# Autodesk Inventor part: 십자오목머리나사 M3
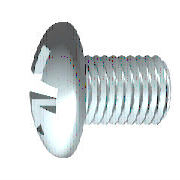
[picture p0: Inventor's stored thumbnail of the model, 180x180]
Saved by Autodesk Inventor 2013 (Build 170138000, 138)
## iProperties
Created: 2012-02
Part Number: 십자오목머리나사 M3
Material: 강철, 연강
Description: 십자 오목 머리 나사
Document SubType Name: Modeling
Standard: KS B 1023
Designer: mduedu
Standards Organization: KS
Language: ko-KR
Size Designation: A  M 3 x 6 - H
Categories: <MemberInstance><Categories><Category DisplayName="조임쇠" InternalName="e4da775c-781d-43d5-af7c-5136215cf5a6" Mnemonic="FSTN"><Category DisplayName="볼트" InternalN
Density: 7.86 g/cm^3
Mass: 0.662366 g
Surface Area: 1.40196 cm^2
Volume: 0.0842705 cm^3
IsCustomPart: 0
Author: mduedu
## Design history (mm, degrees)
body "Solid1"
workplane "Work Plane3"
sketch "스케치2"
  geometry: L1 (-3.72, 0)-(3.72, 0) reference; L2 (0, -3.72)-(0, 3.72) reference; L3 (0, 1.5)-(0, 0); L4 (0, 0)-(1.5, 0); L5 (0, 0)-(1.879, 1.879); L6 (0.253, 1.479)-(0.261, 0.456); L7 (1.479, 0.253)-(0.456, 0.261); L8 (0.253, -1.479)-(0.261, -0.456); L9 (1.479, -0.253)-(0.456, -0.261); L10 (-0.253, 1.479)-(-0.261, 0.456); L11 (-1.479, 0.253)-(-0.456, 0.261); L12 (-1.479, -0.253)-(-0.456, -0.261); L13 (-0.253, -1.479)-(-0.261, -0.456); A1 r 0.45 centre (0, 0) between (0.45, 0) and (0, 0.45); A2 r 1.5 centre (0, 0) between (1.5, 0) and (1.479, 0.253); A3 r 1.5 centre (0, 0) between (0.253, 1.479) and (0, 1.5); A4 r 1.5 centre (0, 0) between (1.479, 0.253) and (0.253, 1.479); A5 r 1.5 centre (0, 0) between (0, -1.5) and (0.253, -1.479); A6 r 1.5 centre (0, 0) between (0.253, -1.479) and (1.479, -0.253); A7 r 1.5 centre (0, 0) between (1.479, -0.253) and (1.5, 0); A8 r 1.5 centre (0, 0) between (-1.479, 0.253) and (-1.5, 0); A9 r 1.5 centre (0, 0) between (-0.253, 1.479) and (-1.479, 0.253); A10 r 1.5 centre (0, 0) between (0, 1.5) and (-0.253, 1.479); A11 r 1.5 centre (0, 0) between (-1.5, 0) and (-1.479, -0.253); A12 r 1.5 centre (0, 0) between (-1.479, -0.253) and (-0.253, -1.479); A13 r 1.5 centre (0, 0) between (-0.253, -1.479) and (0, -1.5); A14 r 0.525 centre (0, 0) between (0.525, 0) and (0, 0.525); A15 r 0.197 centre (0.457, 0.457) between (0.261, 0.456) and (0.456, 0.261); A16 r 0.197 centre (0.457, -0.457) between (0.456, -0.261) and (0.261, -0.456); A17 r 0.197 centre (-0.457, 0.457) between (-0.456, 0.261) and (-0.261, 0.456); A18 r 0.197 centre (-0.457, -0.457) between (-0.261, -0.456) and (-0.456, -0.261); 1 further point
  constraints: 38 point on circle, 22 end point, 19 symmetric about line, 18 centre point, 4 coincident, 3 collinear, 3 point on line, 3 tangent, 1 perpendicular, 21 other
  dimensions: "d4" = 45 deg angle of L5 L4; "d5" = 0.9 diameter of A1 (= 0.3 x SDM); "d6" = 3 diameter of A4 (= SDM); "d7" = 0.2525 distance from line of L6.start L3 (= 0.5 x SBR); "d14" = 1.05 diameter of A14 (= 0.35 x SDM)
extrude "슬롯" join sketch "스케치2" taper "d15" = 5 deg; stored distance "d54" = 10
revolve "절단부" stored, may be unused: angle "d56" = 90 deg
revolve "본체" stored, may be unused: angle "d18" = 90 deg
workplane "Work Plane1"
sketch "스케치1"
  geometry: L1 (6, 0)-(6, 1.5); L2 (6, 1.5)-(1, 1.5); L3 (3.962, 5.08)-(3.962, 5.08); L4 (-2.4, 0)-(-2.4, 2.59); L5 (-2.2, 1.4)-(-1.036, 0.82); L6 (-1.036, 0.82)-(-0.6, 0); L7 (-0.6, 0)-(6, 0); L8 (-4.305, 0)-(7.717, 0) reference; L9 (0, -1.016)-(0, 6.096) reference; L10 (-2.2, 1.4)-(-2.4, 1.5); L11 (-1.636, 2.657)-(-2.4, 2.59); L12 (-1.636, 2.657)-(0, 2.8); L13 (0, 2.8)-(0, 1.347); L14 (0, 1.347)-(0.693, 1.347); L15 (0.693, 1.347)-(1, 1.5); L16 (1, 1.5)-(0, 1.5); A1 r 5 centre (2.6, 0) between (-1.636, 2.657) and (-2.4, 0)
  constraints: 28 end point, 5 point on line, 4 collinear, 4 point on circle, 3 parallel, 2 perpendicular, 1 centre point, 1 horizontal, 1 tangent
  dimensions: "d1" = 3 diameter of L2 L7 (= GD); "d2" = 1.8 distance from line of L6.end L4 (= STI); "d11" = 3 diameter of L10.end L7 (= SDM); "d12" = 62 deg angle of L6 L7; "d13" = 26.5 deg angle of L5 L7; "d17" = 5.6 diameter of L12.end L7 (= KOD); "d19" = 5 deg angle of L12 L7 (= KEWI); "d20" = 2.4 distance between parallel lines of L4 L13 (= KOH); "d21" = 5 radius of A1 (= KR); "d23" = 2.6935 diameter of L14 L7 (= BDM); "d24" = 5 distance of L1.end L2.end (= GEL); "d25" = 0.30673 horizontal distance of L14.end L2.end (= GAL); "d28" = 6 distance between parallel lines of L1 L13 (= NLG)
fillet "모깎기1" dims "d29" = 1.2 (= RR)
fillet "모깎기2" dims "d16" = 0.101 (= 0.2 x SBR)
feature "스레드" dims "d8" = 5 (= GEL), "d9" = 0
chamfer "모따기1" distance "d26" = 0.30673 (= -0.5 x SPD + 0.5 x GD); stored, may be unused: second distance "d27" = 0.30683 (computed from GUL), angle "d78" = 45 deg
other parameters: "GD" = 3 (= NND) [user parameter; used in 2 equation terms], "NLG" = 6 [user parameter; used in 1 equation term], "GEL" = 5 [user parameter; used in 2 equation terms], "KOD" = 5.6 [user parameter; used in 1 equation term], "KOH" = 2.4 [user parameter; used in 2 equation terms], "SDM" = 3 [user parameter; used in 4 equation terms], "STI" = 1.8 [user parameter; used in 1 equation term], "SBR" = 0.505 [user parameter; used in 2 equation terms], "GAL" = 0.30673 (= 0.61345 x PTC) [user parameter; used in 1 equation term], "SPD" = 2.38655 (= NND - 1.2269 x PTC) [user parameter; used in 1 equation term], "KEWI" = 5 deg [user parameter; used in 1 equation term], "d3" = -2.4 (= -KOH), "d10" = 0, "KR" = 5 [user parameter; used in 1 equation term], "BDM" = 2.6935 [user parameter; used in 1 equation term], "GUL" = 0.30673 (= 0.61345 x PTC) [user parameter; used in 1 equation term], "RR" = 1.2 [user parameter; used in 1 equation term], "d79" = 0, "d80" = 0, "PTC" = 0.5 [user parameter; used in 5 equation terms], "THREADDIA" = 3 [user parameter; used in 1 equation term], "TOA" = 30 deg [user parameter], "NND" = 3 [user parameter; used in 2 equation terms], "GD1" = 2.38655 (= THREADDIA - 1.2269 x PTC) [user parameter]
